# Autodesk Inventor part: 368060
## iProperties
Created: 2006-06
Part Number: 368060
Material: 8.8 vz
Description: Sperrzahnmutter
Document SubType Name: Modeling
Designer: I.Baliuc
Density: 7.85 g/cm^3
Mass: 2.46844 g
Surface Area: 3.83121 cm^2
Volume: 0.314452 cm^3
Abmessung: M5
Author: T.Messerschmitt
Revision Number: 368060
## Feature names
1. Basis1
